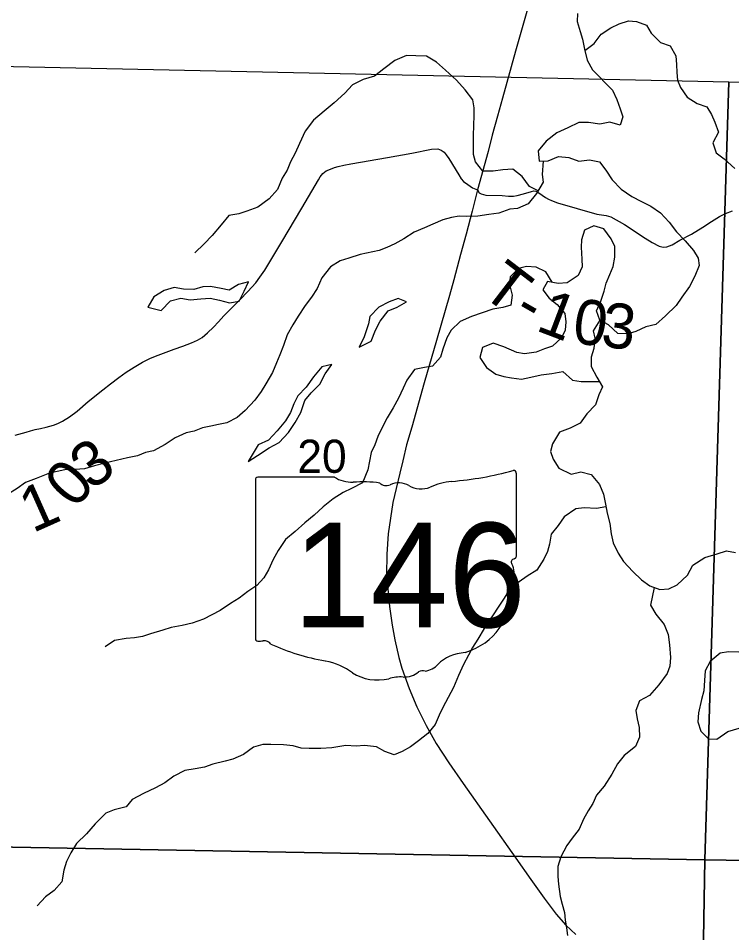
# Model space of a CAD drawing. Extents: x 0 to 34, y 0 to 22.
# Drawn here: x 6.508 to 7.409, y 17.478 to 18.632 of the extents above; entities that cross this region are included whole.
import ezdxf

# ---------------------------------------------------------------- set-up
doc = ezdxf.new("R2010")
doc.units = 0
for name, color, linetype in [('GM_X_Corporation', 7, 'Continuous'), ('GM_X_Minor_Lake', 7, 'Continuous'), ('GM_X_Minor_River', 7, 'Continuous'), ('GM_X_Section_Text', 7, 'Continuous'), ('GM_X_State_Location', 7, 'Continuous'), ('GM_X_State_Route', 7, 'Continuous'), ('GM_X_State_Shield', 7, 'Continuous'), ('GM_X_Township_Road', 7, 'Continuous'), ('GM_X_Township_Road_Text', 7, 'Continuous')]:
    doc.layers.add(name, color=color, linetype=linetype)

msp = doc.modelspace()

# ---------------------------------------------------------------- linework, layer by layer
at = {"layer": 'GM_X_Corporation'}
for points in [[(6.4033, 18.5738), (7.4054, 18.552), (7.375, 17.5696), (6.3854, 17.5878)], [(7.4054, 18.552), (8.4197, 18.5333), (8.4063, 17.5538), (7.375, 17.5696)], [(6.3854, 17.5878), (7.375, 17.5696), (7.3577, 16.5425), (6.3626, 16.5761)], [(7.375, 17.5696), (8.4063, 17.5538), (8.3875, 16.5502), (7.3577, 16.5425)]]:
    msp.add_lwpolyline(points, close=True, dxfattribs=at)
at = {"layer": 'GM_X_Minor_Lake'}
for points in [[(6.7916, 18.2846), (6.7931, 18.2877), (6.7988, 18.2998), (6.7863, 18.2964), (6.7742, 18.2892), (6.7644, 18.2911), (6.7508, 18.2938), (6.741, 18.2934), (6.7296, 18.29), (6.7168, 18.2904), (6.7047, 18.2923), (6.6922, 18.2885), (6.6793, 18.2806), (6.6717, 18.2677)], [(6.6717, 18.2677), (6.6883, 18.2635), (6.7001, 18.2756), (6.7133, 18.279), (6.725, 18.2771), (6.7387, 18.2783), (6.7504, 18.279), (6.7621, 18.2763), (6.7746, 18.2729), (6.7871, 18.2752), (6.7916, 18.2846)], [(6.9941, 18.2762), (6.9879, 18.2787), (6.9765, 18.2745), (6.9636, 18.2677), (6.9519, 18.256), (6.9504, 18.2465), (6.945, 18.2302), (6.9386, 18.2173)], [(6.9386, 18.2173), (6.9537, 18.2249), (6.959, 18.2385), (6.9651, 18.2499), (6.975, 18.2628), (6.9867, 18.2677), (6.9984, 18.2745), (6.9941, 18.2762)], [(6.7984, 18.0727), (6.8101, 18.0803), (6.8249, 18.0901), (6.8374, 18.0966), (6.8491, 18.1094), (6.8579, 18.1219), (6.8647, 18.1348), (6.87, 18.1496), (6.878, 18.1594), (6.889, 18.1704), (6.8958, 18.1833), (6.9041, 18.1954), (6.8984, 18.1941)], [(6.8984, 18.1941), (6.8913, 18.1924), (6.881, 18.1795), (6.8716, 18.1666), (6.8609, 18.1557), (6.856, 18.1454), (6.8518, 18.1348), (6.8454, 18.1242), (6.8351, 18.1113), (6.8242, 18.0996), (6.8109, 18.0936), (6.7984, 18.0727)]]:
    msp.add_lwpolyline(points, dxfattribs=at)
at = {"layer": 'GM_X_Minor_River'}
for points in [[(7.2143, 18.6385), (7.2139, 18.6286)], [(7.2139, 18.6286), (7.2177, 18.6157), (7.2207, 18.6059), (7.2233, 18.5934), (7.2267, 18.5797), (7.2331, 18.5672), (7.2584, 18.5418), (7.264, 18.53), (7.2681, 18.5182), (7.2715, 18.508), (7.2681, 18.4974), (7.2553, 18.5012), (7.2424, 18.4986), (7.2284, 18.5009), (7.2159, 18.5009), (7.2019, 18.4941), (7.1883, 18.4876), (7.1747, 18.4774), (7.1648, 18.4649), (7.1659, 18.4521), (7.1773, 18.4524), (7.1901, 18.4581), (7.2034, 18.4565), (7.2162, 18.452), (7.2295, 18.4535), (7.2423, 18.4512), (7.2499, 18.4406), (7.2581, 18.4284), (7.2695, 18.4167), (7.2831, 18.4075), (7.2952, 18.4011), (7.3069, 18.395), (7.3193, 18.3866), (7.3299, 18.3749), (7.3393, 18.3627), (7.3503, 18.3514), (7.3608, 18.3392), (7.3665, 18.3297), (7.368, 18.3202), (7.3623, 18.3066), (7.3558, 18.2937), (7.346, 18.2801), (7.3388, 18.2699), (7.3255, 18.2566), (7.3134, 18.2457), (7.3005, 18.2426), (7.288, 18.237), (7.2782, 18.234), (7.2653, 18.2343), (7.2536, 18.2454), (7.2427, 18.2511), (7.234, 18.2378), (7.2362, 18.2283), (7.235, 18.2154), (7.2316, 18.2044), (7.2316, 18.1927), (7.2388, 18.1794), (7.2459, 18.1669), (7.2414, 18.1571), (7.2372, 18.1442), (7.2262, 18.1328), (7.2175, 18.1211), (7.205, 18.1147), (7.1917, 18.1097), (7.1826, 18.095), (7.18, 18.0855), (7.1837, 18.0756), (7.1909, 18.0643)], [(7.2237, 18.5916), (7.2354, 18.6005), (7.2441, 18.6123), (7.2562, 18.6202), (7.2668, 18.6255), (7.2786, 18.6293), (7.2888, 18.6285), (7.3016, 18.6236), (7.3073, 18.6137), (7.319, 18.6019), (7.3315, 18.5978), (7.3386, 18.5852), (7.3394, 18.5742), (7.3397, 18.564), (7.3408, 18.5545), (7.3442, 18.5451), (7.3529, 18.5329), (7.3654, 18.5249), (7.3778, 18.5207), (7.3835, 18.5109), (7.3876, 18.5014), (7.3925, 18.4885), (7.3853, 18.4753), (7.3894, 18.4624), (7.3996, 18.4551), (7.4132, 18.4426)], [(7.1645, 18.4147), (7.1538, 18.4202), (7.1443, 18.4327), (7.1326, 18.4419), (7.1198, 18.4411), (7.108, 18.4392), (7.0948, 18.4393), (7.0854, 18.451), (7.0831, 18.4605), (7.0828, 18.4741), (7.0828, 18.4844), (7.0832, 18.4969), (7.0836, 18.5098), (7.084, 18.5193), (7.0821, 18.5295), (7.0723, 18.542), (7.0614, 18.5545), (7.0478, 18.5671), (7.0361, 18.5769), (7.0236, 18.5845), (7.01, 18.5849), (6.9983, 18.5853), (6.9835, 18.5793), (6.9695, 18.5687), (6.9578, 18.5592), (6.9438, 18.5551), (6.9301, 18.5483), (6.9203, 18.5377), (6.907, 18.5255), (6.8945, 18.515), (6.8809, 18.5036), (6.8703, 18.49), (6.8634, 18.4744), (6.8578, 18.4623), (6.8517, 18.451), (6.8475, 18.4407), (6.8414, 18.4305), (6.8354, 18.4161), (6.8247, 18.4044), (6.8107, 18.3938), (6.7967, 18.3889), (6.7865, 18.3855), (6.774, 18.3836), (6.7642, 18.3715), (6.7528, 18.3582), (6.743, 18.3476), (6.7312, 18.3363)], [(7.1711, 18.4522), (7.1697, 18.435), (7.1708, 18.4255), (7.1624, 18.4111), (7.1522, 18.3982), (7.1386, 18.3922), (7.1288, 18.3915), (7.1151, 18.3862), (7.1023, 18.3847), (7.0886, 18.3824), (7.0747, 18.382), (7.0648, 18.3824), (7.055, 18.3809), (7.0444, 18.3779), (7.0315, 18.3726), (7.0209, 18.3677), (7.0081, 18.3624), (6.9948, 18.3541), (6.9838, 18.3477), (6.9736, 18.3428), (6.9638, 18.3394), (6.9399, 18.3341), (6.9256, 18.3296), (6.9146, 18.3262), (6.9025, 18.3186), (6.8915, 18.3046), (6.8854, 18.2913), (6.8782, 18.2803), (6.8702, 18.2697), (6.8615, 18.2561), (6.8547, 18.2455), (6.8475, 18.2326), (6.8429, 18.2194), (6.8384, 18.2076), (6.8342, 18.1974), (6.8289, 18.1853), (6.8205, 18.1709), (6.8148, 18.161), (6.8069, 18.1504), (6.7944, 18.1372), (6.7845, 18.1285), (6.7713, 18.1217), (6.761, 18.1194), (6.7512, 18.1175), (6.7406, 18.1153), (6.73, 18.1111), (6.7202, 18.1088), (6.7062, 18.1028), (6.6937, 18.0941), (6.6789, 18.0862), (6.6687, 18.0839), (6.6585, 18.0801), (6.646, 18.0775), (6.6173, 18.0707), (6.6044, 18.0673), (6.5915, 18.0635), (6.5798, 18.0628), (6.567, 18.0624), (6.5473, 18.058)], [(7.2427, 18.2511), (7.2382, 18.2628), (7.2439, 18.2753), (7.248, 18.2878), (7.2507, 18.298), (7.2553, 18.309), (7.2594, 18.3189), (7.2614, 18.3306), (7.2614, 18.3443), (7.2569, 18.3538), (7.2474, 18.3667), (7.235, 18.3705), (7.2232, 18.3648), (7.2194, 18.3527), (7.219, 18.3432), (7.2198, 18.3284), (7.2201, 18.3186), (7.2152, 18.3076), (7.2012, 18.2985), (7.1898, 18.2977), (7.1766, 18.3), (7.1705, 18.2894), (7.1785, 18.2792), (7.1886, 18.2712), (7.1981, 18.2595), (7.1996, 18.2492), (7.1988, 18.2386), (7.1942, 18.2291), (7.1829, 18.2185), (7.1727, 18.2151), (7.1621, 18.211), (7.1473, 18.2087), (7.1375, 18.2103), (7.1212, 18.2175), (7.108, 18.222), (7.0944, 18.2168), (7.091, 18.2039), (7.0993, 18.1914), (7.111, 18.183), (7.1212, 18.18), (7.131, 18.1784), (7.1435, 18.1769), (7.1552, 18.1792), (7.1684, 18.1822), (7.182, 18.184), (7.1957, 18.1863), (7.2081, 18.1753), (7.2191, 18.1738), (7.242, 18.1738)], [(7.1825, 18.299), (7.1744, 18.3122), (7.1619, 18.3183), (7.1498, 18.319), (7.14, 18.3164), (7.1293, 18.3058), (7.1286, 18.2963), (7.1319, 18.2827), (7.13, 18.2702), (7.1202, 18.2671), (7.1073, 18.2649), (7.0937, 18.2604), (7.0805, 18.2558), (7.0661, 18.2494), (7.0547, 18.2388), (7.0494, 18.229), (7.0441, 18.2146), (7.0414, 18.2047), (7.0312, 18.1933), (7.021, 18.1915), (7.0085, 18.1888), (6.9986, 18.1756), (6.9941, 18.1653), (6.9884, 18.1528), (6.9815, 18.1403), (6.974, 18.1278), (6.9683, 18.1172), (6.9622, 18.1044), (6.9584, 18.0938), (6.9538, 18.0839), (6.9493, 18.0622)], [(6.9493, 18.0622), (6.9428, 18.0458), (6.9288, 18.0386), (6.9182, 18.0336), (6.9057, 18.0256), (6.8929, 18.0153), (6.8819, 18.005), (6.8698, 17.9951), (6.8577, 17.9845), (6.8457, 17.9742), (6.8362, 17.9605), (6.8298, 17.9488), (6.8242, 17.9359), (6.8182, 17.926), (6.8095, 17.9161), (6.7981, 17.9085), (6.7868, 17.9001), (6.7762, 17.8936), (6.763, 17.8845), (6.7418, 17.8738), (6.7275, 17.8684), (6.715, 17.8657), (6.7013, 17.863), (6.6904, 17.8599), (6.6749, 17.8553), (6.6647, 17.8519), (6.6548, 17.85), (6.6442, 17.8492), (6.6295, 17.8465), (6.6177, 17.8388)], [(7.1909, 18.0643), (7.2062, 18.0566), (7.2187, 18.0597), (7.2316, 18.0563), (7.2419, 18.0438), (7.2472, 18.0313), (7.2495, 18.0188), (7.2518, 18.0075), (7.2553, 17.9946), (7.2568, 17.9813), (7.2595, 17.97), (7.2656, 17.9571), (7.2725, 17.9465), (7.2842, 17.9337), (7.2952, 17.9235), (7.3055, 17.9159), (7.3184, 17.911), (7.3297, 17.9118), (7.3403, 17.9168), (7.3532, 17.929), (7.3599, 17.9419), (7.375, 17.9514), (7.3906, 17.956), (7.4023, 17.9598), (7.414, 17.958)], [(6.5473, 18.058), (6.5308, 18.0512), (6.5172, 18.0462), (6.5066, 18.0386), (6.4945, 18.031), (6.4839, 18.0283), (6.4707, 18.0259), (6.4578, 18.0282), (6.446, 18.0308), (6.4351, 18.0334), (6.4256, 18.0368), (6.4146, 18.0417), (6.404, 18.0416), (6.393, 18.0404), (6.3801, 18.0381), (6.3692, 18.0369), (6.3589, 18.0339), (6.3332, 18.0254), (6.3196, 18.0208)], [(7.2502, 18.0155), (7.2382, 18.0135), (7.2227, 18.0142), (7.2124, 18.013), (7.1973, 18.0027), (7.1898, 17.9921), (7.1811, 17.9811), (7.1789, 17.9685), (7.1766, 17.9591), (7.1717, 17.9492), (7.1631, 17.9355), (7.1506, 17.9279), (7.1408, 17.9207), (7.1294, 17.9123), (7.1215, 17.9001), (7.1151, 17.8899), (7.1068, 17.8777), (7.0963, 17.8617), (7.0883, 17.8485), (7.0819, 17.8378), (7.0767, 17.8283), (7.0703, 17.8162), (7.0642, 17.8025), (7.0575, 17.7873), (7.0511, 17.7748), (7.0443, 17.7619), (7.0394, 17.7524), (7.0345, 17.7406), (7.0251, 17.7292), (7.0134, 17.7201), (7.0032, 17.7125), (6.993, 17.7064), (6.9828, 17.7021), (6.971, 17.7063), (6.9604, 17.7123), (6.9452, 17.7141), (6.9346, 17.7134), (6.9218, 17.7141), (6.904, 17.711), (6.89, 17.7105), (6.8752, 17.7105), (6.8654, 17.7108), (6.8551, 17.7135), (6.843, 17.7149), (6.8271, 17.7152), (6.8169, 17.7152), (6.8052, 17.7121), (6.7923, 17.7026), (6.7791, 17.6969), (6.7692, 17.6942), (6.7537, 17.6903), (6.7431, 17.6869), (6.7314, 17.6846), (6.7182, 17.6826), (6.7045, 17.6754), (6.6932, 17.667), (6.6815, 17.6605), (6.666, 17.6536), (6.652, 17.646), (6.6441, 17.6365), (6.629, 17.6327), (6.6184, 17.6285), (6.6051, 17.6151), (6.5942, 17.6026), (6.5814, 17.5904), (6.5742, 17.5786), (6.5689, 17.5676), (6.5656, 17.5566), (6.563, 17.5418), (6.5532, 17.5308), (6.5426, 17.5228), (6.532, 17.5114)], [(7.311, 17.9138), (7.3063, 17.8913), (7.3132, 17.8799), (7.3238, 17.8667), (7.3288, 17.8542), (7.3307, 17.8413), (7.3319, 17.8254), (7.3308, 17.8144), (7.3274, 17.8049), (7.3172, 17.7909), (7.3051, 17.7772), (7.2927, 17.7703), (7.2878, 17.7582), (7.2897, 17.7476), (7.2924, 17.737), (7.2928, 17.7248), (7.2875, 17.7127), (7.2732, 17.7013), (7.2649, 17.691), (7.2577, 17.6777), (7.2479, 17.6629), (7.2385, 17.6515), (7.2336, 17.6409), (7.2279, 17.6314), (7.2219, 17.6211), (7.2163, 17.6086), (7.2076, 17.5972), (7.2008, 17.5877), (7.1933, 17.5736), (7.1895, 17.5611), (7.1896, 17.5486), (7.1904, 17.5391), (7.1923, 17.5236), (7.195, 17.5137), (7.1977, 17.5031), (7.1988, 17.4933), (7.2004, 17.4838), (7.2015, 17.4743)], [(7.4182, 17.8318), (7.4049, 17.8325), (7.3943, 17.8306), (7.3819, 17.8203), (7.3755, 17.8085), (7.3747, 17.796), (7.374, 17.7831), (7.371, 17.7721), (7.3673, 17.7554), (7.3662, 17.744), (7.37, 17.7323), (7.3799, 17.7225), (7.3901, 17.7221), (7.4041, 17.7317), (7.4185, 17.7359)]]:
    msp.add_lwpolyline(points, dxfattribs=at)
at = {"layer": 'GM_X_State_Route'}
msp.add_lwpolyline([(7.1536, 18.6526), (7.1359, 18.591), (7.1194, 18.5314), (7.1133, 18.5088), (7.1065, 18.4848), (7.1013, 18.4642), (7.0881, 18.416), (7.0813, 18.3887), (7.0737, 18.3599), (7.0666, 18.3342), (7.0583, 18.302), (7.0525, 18.2823), (7.0361, 18.2254), (7.0206, 18.172), (7.005, 18.1161), (6.9984, 18.0937), (6.9937, 18.0737), (6.9898, 18.058), (6.9854, 18.0388), (6.9811, 18.0211), (6.975, 17.9814), (6.9734, 17.9559), (6.9732, 17.9296), (6.9769, 17.8896), (6.9803, 17.866), (6.9836, 17.8477), (6.9887, 17.8253), (6.9924, 17.8118), (7.0016, 17.786), (7.0112, 17.7628), (7.023, 17.7393), (7.0359, 17.7166), (7.0517, 17.6924), (7.0701, 17.6661), (7.1364, 17.5716), (7.1552, 17.5448), (7.1722, 17.5213), (7.1874, 17.5012), (7.1997, 17.4872), (7.2122, 17.4752)], dxfattribs=at)
at = {"layer": 'GM_X_State_Shield'}
for p, q in [((6.8075, 18.0496), (6.8075, 17.8494)), ((6.9073, 18.053), (6.8107, 18.053)), ((7.1371, 17.9533), (7.1371, 18.058)), ((7.1371, 17.9533), (7.1371, 17.9533))]:
    msp.add_line(p, q, dxfattribs=at)
for centre, major_axis, start_param, end_param in [((7.0197, 18.3258), (0.3495, 0), 4.814394, 5.042369), ((7.1334, 18.0584), (0.00367, 0), 6.141152, 7.989035), ((6.8113, 18.05), (0.00382, 0), 1.712693, 3.28349), ((6.9303, 18.0762), (0.037, 0), 4.042523, 4.731795), ((6.9425, 17.9406), (0.133, 0), 1.404758, 1.657858), ((6.9727, 18.051), (0.0107, 0), 3.836095, 5.185415), ((6.9884, 18.0279), (0.0222, 0), 0.950623, 2.079405), ((7.0171, 18.0596), (0.0267, 0), 4.081561, 5.145723), ((7.0643, 17.9919), (0.0703, 0), 1.699011, 2.107814), ((7.1362, 17.9456), (0.00568, 0), 1.883978, 3.671073), ((7.1332, 17.9529), (0.00393, 0), 5.05454, 6.418171), ((7.1001, 17.9324), (0.0341, 0), 5.934695, 6.695948), ((7.1502, 17.9095), (0.0248, 0), 2.387724, 3.262537), ((7.0393, 17.8961), (0.0874, 0), 5.101752, 6.440018), ((6.8113, 17.849), (0.00385, 0), 3.00124, 4.508301), ((6.8119, 17.8695), (0.0294, 0), 4.665946, 4.897461), ((6.8179, 17.8379), (0.0106, 0), 0.519207, 1.627899), ((6.9517, 18.0177), (0.2524, 0), 4.195997, 4.488961), ((7.0761, 17.7932), (0.0479, 0), 1.647645, 2.488434), ((6.8765, 17.7595), (0.079, 0), 0.823519, 1.323587), ((6.9945, 17.8219), (0.0267, 0), 4.691044, 5.507374), ((7.0187, 17.8025), (0.00752, 0), 1.147584, 2.315152), ((7.0155, 17.83), (0.0282, 0), 4.937069, 5.64225), ((6.9619, 17.8369), (0.0501, 0), 4.026481, 4.996735), ((6.9909, 17.7677), (0.0412, 0), 1.495662, 1.94098)]:
    msp.add_ellipse(centre, major_axis=major_axis, ratio=0.8, start_param=start_param, end_param=end_param, dxfattribs=at)
at = {"layer": 'GM_X_Township_Road'}
for points in [[(6.5042, 18.1058), (6.5133, 18.1085), (6.5179, 18.1099), (6.5233, 18.1115), (6.5293, 18.113), (6.5361, 18.1144), (6.5434, 18.1161), (6.5523, 18.1187), (6.5578, 18.1206), (6.5639, 18.1237), (6.5726, 18.129), (6.5823, 18.1364), (6.5963, 18.1485), (6.6149, 18.1634), (6.6244, 18.171), (6.6349, 18.179), (6.6443, 18.1857), (6.6542, 18.192), (6.6649, 18.198), (6.675, 18.2031), (6.6845, 18.207), (6.705, 18.2145), (6.7159, 18.2182), (6.7266, 18.2224), (6.7342, 18.226), (6.7401, 18.2295), (6.7472, 18.2353), (6.7545, 18.2422), (6.761, 18.2493), (6.7675, 18.2567), (6.7877, 18.2767), (6.7978, 18.2873), (6.8079, 18.2983), (6.8133, 18.3056), (6.8193, 18.3145), (6.841, 18.3503), (6.8663, 18.3927), (6.887, 18.4285), (6.8895, 18.4324), (6.8926, 18.4365), (6.897, 18.4397), (6.9025, 18.4421), (6.9073, 18.4439), (6.9122, 18.4454), (6.9191, 18.447), (6.9279, 18.4486), (6.9744, 18.4565), (7.005, 18.4621), (7.0298, 18.4673), (7.0381, 18.4675), (7.0422, 18.466), (7.0457, 18.4635), (7.0485, 18.4602), (7.0518, 18.4555), (7.0643, 18.4347), (7.0675, 18.4298), (7.0703, 18.4264), (7.0757, 18.4224), (7.0819, 18.4185), (7.0881, 18.416)], [(7.0881, 18.416), (7.0903, 18.4122), (7.0926, 18.4107), (7.0986, 18.4092), (7.119, 18.4088), (7.1272, 18.4079), (7.1335, 18.4079), (7.1382, 18.4085), (7.1463, 18.4109), (7.1563, 18.4139), (7.1593, 18.4144), (7.1618, 18.414), (7.1656, 18.412), (7.174, 18.4062), (7.1776, 18.4042), (7.1813, 18.4023), (7.1892, 18.3993), (7.2387, 18.3849), (7.2506, 18.3834), (7.2566, 18.3817), (7.2738, 18.3722), (7.2997, 18.3549), (7.3085, 18.3495), (7.3174, 18.3445), (7.3224, 18.3434), (7.3272, 18.3438), (7.3338, 18.3463), (7.3434, 18.3521), (7.3582, 18.36), (7.3725, 18.3686), (7.3834, 18.376), (7.3935, 18.382), (7.4014, 18.386), (7.4099, 18.3895)]]:
    msp.add_lwpolyline(points, dxfattribs=at)

# ---------------------------------------------------------------- texts
at = {"layer": 'GM_X_Section_Text'}
msp.add_text('20', height=0.04186, rotation=0, dxfattribs=at).set_placement((6.8605, 18.0584))
at = {"layer": 'GM_X_State_Location'}
for s in ['s', 'r']:
    msp.add_text(s, height=0.000189, dxfattribs=at).set_placement((6.9686, 17.9362))
msp.add_text('146', height=0.000189, rotation=0, dxfattribs=at).set_placement((6.9017, 17.9224))
at = {"layer": 'GM_X_State_Shield'}
msp.add_text('146', height=0.13184, dxfattribs=at).set_placement((6.8549, 17.8635))
at = {"layer": 'GM_X_Township_Road_Text'}
for s, rotation, p in [('T', 322.5678, (7.0904, 18.2849)), ('1', 339.251, (7.1601, 18.2388)), ('-', 330.2947, (7.1311, 18.2545)), ('0', 352.1511, (7.2063, 18.223)), ('3', 353.6434, (7.2426, 18.218)), ('3', 35.4282, (6.5999, 18.0354)), ('0', 48.1782, (6.5791, 18.0115)), ('1', 24.044, (6.5262, 17.982))]:
    msp.add_text(s, height=0.0568, rotation=rotation, dxfattribs=at).set_placement(p)

doc.saveas('drawing.dxf')
